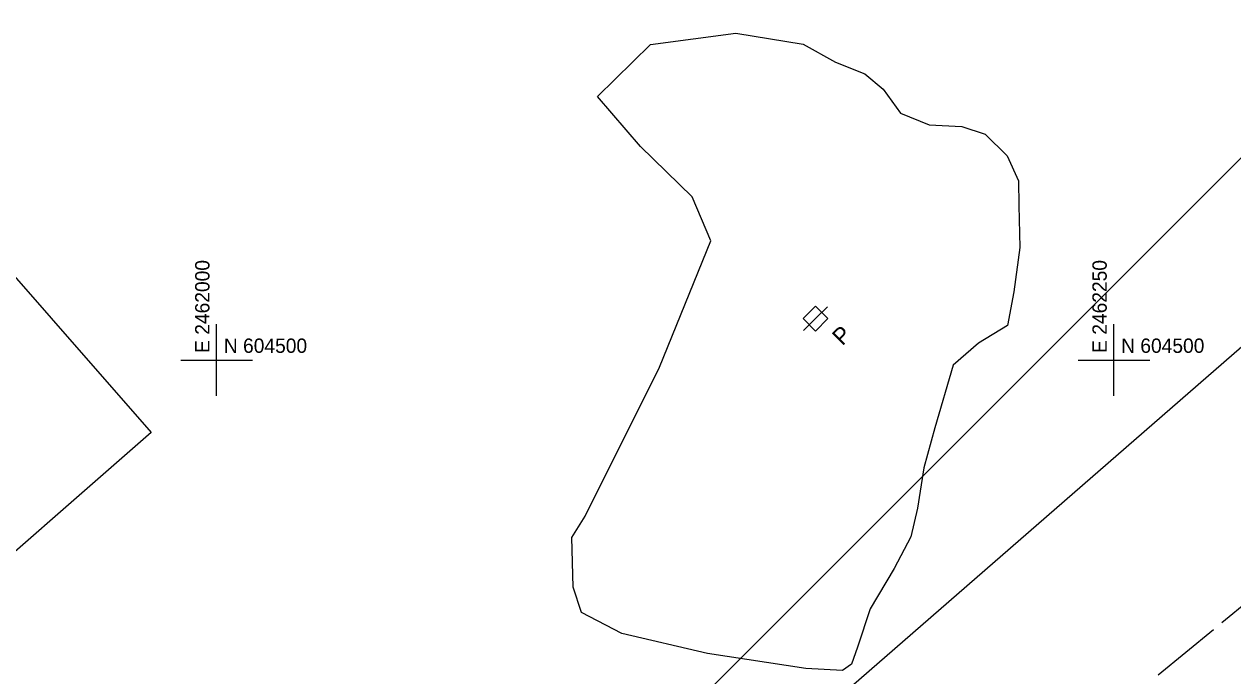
# Model space of a CAD drawing. Extents: x 2443269 to 2494951, y 591171 to 622130.
# Drawn here: x 2461946.4 to 2462283.1, y 604412 to 604593.6 of the extents above; entities that cross this region are included whole.
import ezdxf

# ---------------------------------------------------------------- set-up
doc = ezdxf.new("R2010")
doc.units = 0
for name, color, linetype in [('SURVEY - CONTROL - Grid', 7, 'Continuous'), ('SURVEY - CONTROL - Grid Text', 7, 'Continuous'), ('SURVEY - CONTROL with Text', 7, 'Continuous'), ('SURVEY - DRAINAGE - Natural Features', 7, 'Continuous'), ('SURVEY - NON-TRANSPORTATION - Features', 7, 'Continuous'), ('SURVEY - PROPERTY - ROW Lines', 7, 'Continuous'), ('SURVEY - UTILITIES - Poles and Miscellaneous with Text', 7, 'Continuous'), ('SURVEY - UTILITIES - Sanitary Sewer with Text', 7, 'Continuous')]:
    doc.layers.add(name, color=color, linetype=linetype)

msp = doc.modelspace()

# ---------------------------------------------------------------- linework, layer by layer
at = {"layer": 'SURVEY - CONTROL - Grid'}
for p, q in [((2462000, 604490), (2462000, 604510)), ((2462250, 604490), (2462250, 604510)), ((2461990, 604500), (2462010, 604500)), ((2462240, 604500), (2462260, 604500))]:
    msp.add_line(p, q, dxfattribs=at)
at = {"layer": 'SURVEY - CONTROL with Text'}
msp.add_lwpolyline([(2461800.88, 604321.534), (2461716.586, 604417.87), (2461897.45, 604576.126), (2461981.744, 604479.79)], close=True, dxfattribs=at)
at = {"layer": 'SURVEY - DRAINAGE - Natural Features'}
msp.add_lwpolyline([(2462136.775, 604418.188), (2462112.907, 604423.762), (2462101.67, 604429.677), (2462099.373, 604436.728), (2462098.957, 604450.498), (2462102.631, 604456.534), (2462123.405, 604497.991), (2462137.657, 604533.25), (2462132.47, 604545.455), (2462118.097, 604559.474), (2462106.096, 604573.463), (2462120.876, 604587.925), (2462144.652, 604591.085), (2462163.418, 604588.033), (2462172.385, 604583.001), (2462180.61, 604579.776), (2462185.692, 604575.451), (2462190.557, 604568.847), (2462198.497, 604565.533), (2462207.608, 604565.054), (2462214.137, 604562.991), (2462220.242, 604556.944), (2462223.395, 604549.979), (2462223.51, 604543.047), (2462223.759, 604531.37), (2462222.106, 604519.044), (2462220.387, 604509.664), (2462212.263, 604504.72), (2462205.167, 604498.529), (2462200.134, 604481.114), (2462197.067, 604469.943), (2462195.233, 604458.759), (2462193.435, 604450.708), (2462188.782, 604441.928), (2462182.106, 604430.704), (2462178.569, 604420.012), (2462176.903, 604415.284), (2462174.416, 604413.506), (2462164.163, 604413.998)], close=True, dxfattribs=at)
at = {"layer": 'SURVEY - NON-TRANSPORTATION - Features'}
msp.add_lwpolyline([(2461875.552, 604146.478), (2462297.817, 604568.743), (2462299.879, 604566.681), (2462297.817, 604564.618), (2462295.754, 604566.681), (2462296.785, 604567.712)], dxfattribs=at)
at = {"layer": 'SURVEY - PROPERTY - ROW Lines'}
msp.add_line((2462832.634, 604980.177), (2461653.501, 603953.054), dxfattribs=at)
at = {"layer": 'SURVEY - UTILITIES - Poles and Miscellaneous with Text'}
for q in [(2462170.153, 604514.873), (2462163.541, 604508.261)]:
    msp.add_line((2462166.847, 604511.567), q, dxfattribs=at)
msp.add_lwpolyline([(2462163.367, 604511.567), (2462166.847, 604515.047), (2462170.327, 604511.567), (2462166.847, 604508.087)], close=True, dxfattribs=at)
at = {"layer": 'SURVEY - UTILITIES - Sanitary Sewer with Text'}
for p, q in [((2462287.782, 604433.097), (2462280.053, 604426.751)), ((2462277.735, 604424.847), (2462262.278, 604412.155))]:
    msp.add_line(p, q, dxfattribs=at)

# ---------------------------------------------------------------- texts
at = {"layer": 'SURVEY - CONTROL - Grid Text'}
for s, p in [('E 2462000', (2461998, 604502)), ('E 2462250', (2462248, 604502))]:
    msp.add_text(s, height=4, rotation=90, dxfattribs=at).set_placement(p)
for p in [(2462002, 604502), (2462252, 604502)]:
    msp.add_text('N 604500', height=4, dxfattribs=at).set_placement(p)
at = {"layer": 'SURVEY - UTILITIES - Poles and Miscellaneous with Text'}
msp.add_text('P', height=4.675, rotation=45, dxfattribs=at).set_placement((2462174.346, 604503.755))

doc.saveas('drawing.dxf')
